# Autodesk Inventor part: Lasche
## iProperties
Created: 2008-01
Part Number: Lasche
Material: Stahl
Document SubType Name: Modeling
Designer: Administrator
Density: 7.85 g/cm^3
Author: Administrator
SBm.TeileNr: -
SBm.TeileRev: 0
SBm.Rohteil: -
SBm.Werkstoff: -
SBm.WerkstNr: -
SBm.Gewicht: 0
SBm.BenennD: -
SBm.BenennE: -
SBm.AenIndex1: 0
SBm.AenDatum1: 01.04.2006
SBm.AenName1: -
SBm.AenIndex2: 0
SBm.AenDatum2: 01.04.2006
SBm.AenName2: -
SBm.InvVersion: 11
SBm.EntstAus: -
SBm.Norm: -
SBm.Hersteller: -
SBm.Groesse: -
SBm.ZchgFormat: -
SBm.TeileKennung: -
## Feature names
1. Rundung2 [Fillet]
